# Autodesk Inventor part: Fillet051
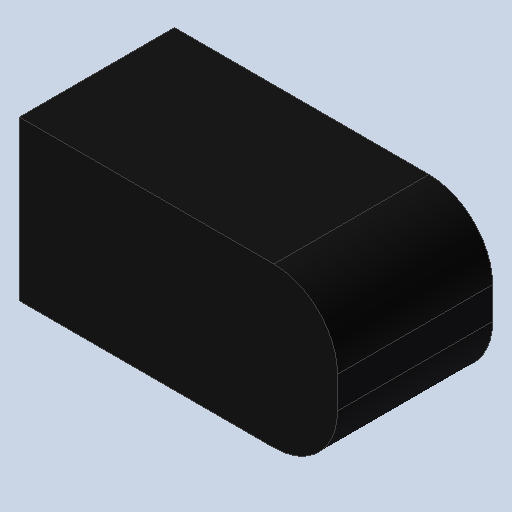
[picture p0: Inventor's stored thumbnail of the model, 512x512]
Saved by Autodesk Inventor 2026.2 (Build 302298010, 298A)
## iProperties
Created: 2026-10
Part Number: Fillet051
Material: Générique
Document SubType Name: Modeling
Designer: mel
Density: 1 g/cm^3
Appearance: Par défaut
Author: mel
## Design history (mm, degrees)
feature "Base1"
node "Solide1"
